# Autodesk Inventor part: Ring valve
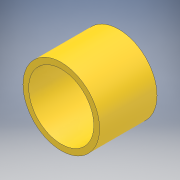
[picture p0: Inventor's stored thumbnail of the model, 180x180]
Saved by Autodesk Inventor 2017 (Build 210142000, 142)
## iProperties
Created: 2020-04
Part Number: Ring valve
Material: Generic
Document SubType Name: Modeling
Designer: user
Density: 1 g/cm^3
Appearance: Default
Author: user
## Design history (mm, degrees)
sketch "Sketch1"
  geometry: C1 r 10 at (0, 0); C2 r 8.5 at (0, 0); 1 further point
  constraints: 2 centre point, 1 coincident
  dimensions: "d0" = 20 diameter of C1; "d1" = 1.5 radial gap between concentric circles of C1 C2
extrude "Extrusion1" new body sketch "Sketch1" distance "d2" = 15; taper "d3" = 0 deg
body "Solid1"
